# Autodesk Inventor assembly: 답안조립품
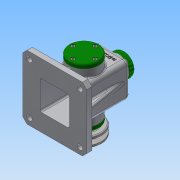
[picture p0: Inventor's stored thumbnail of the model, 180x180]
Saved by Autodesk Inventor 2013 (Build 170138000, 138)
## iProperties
Created: 2018-10
Part Number: 답안조립품
Document SubType Name: Assembly
Designer: Administrator
Author: Administrator
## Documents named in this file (14)
- C:\Users\Administrator\Desktop\481013V1016\답안조립품.iam
- C:\Users\Administrator\Desktop\481013V1016\본체.ipt
- C:\Users\Administrator\Desktop\481013V1016\V-벨트풀리.ipt
- C:\Users\Administrator\Desktop\481013V1016\뒤커버.ipt
- C:\Users\Administrator\Desktop\481013V1016\멈춤링 15 x 1.ipt
- C:\Users\Administrator\Desktop\481013V1016\베어링 15 x 35 x 11.ipt
- C:\Users\Administrator\Desktop\481013V1016\볼트 M4 x 10.ipt
- C:\Users\Administrator\Desktop\481013V1016\볼트 M6 x 12.ipt
- C:\Users\Administrator\Desktop\481013V1016\상부캡.ipt
- C:\Users\Administrator\Desktop\481013V1016\앞커버.ipt
- C:\Users\Administrator\Desktop\481013V1016\오일실 15 25 7.ipt
- C:\Users\Administrator\Desktop\481013V1016\와셔.ipt
- C:\Users\Administrator\Desktop\481013V1016\축.ipt
- C:\Users\Administrator\Desktop\481013V1016\키 5 x 5 x 14.ipt
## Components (1 placed, 1 different names)
1. V-벨트풀리:1 — 플러쉬:1
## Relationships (1: Flush 1)
- 플러쉬:1 [Flush]: V-벨트풀리:1
